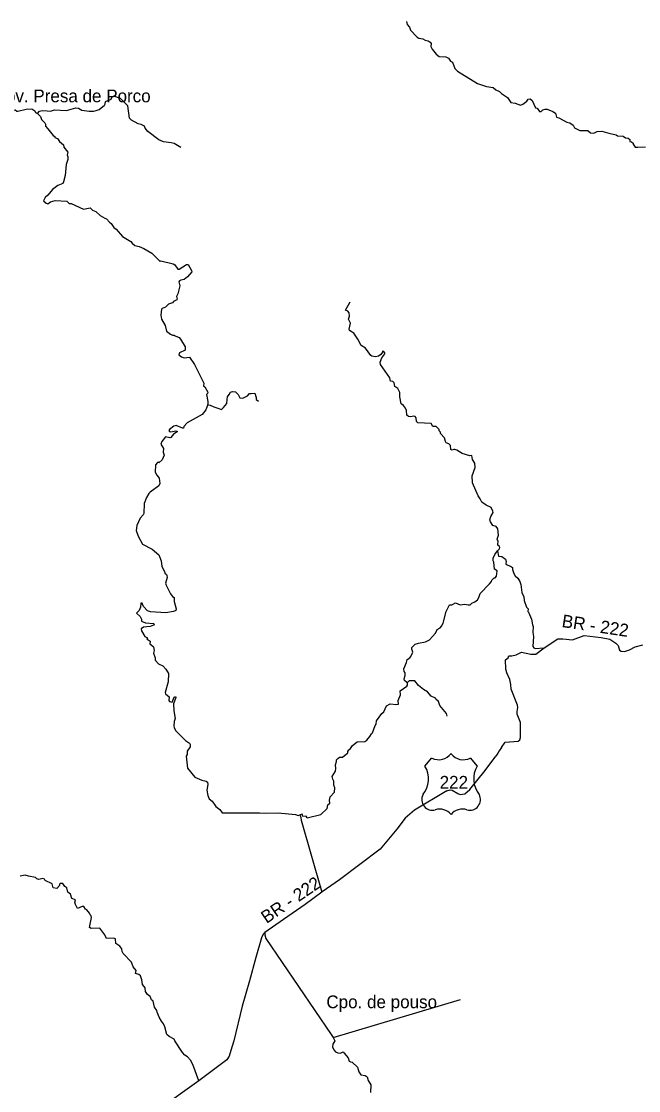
# Model space of a CAD drawing. Extents: x 332 to 501, y 9447 to 9559.
# Drawn here: x 359.78 to 378.21, y 9525.86 to 9557.78 of the extents above; entities that cross this region are included whole.
import ezdxf

# ---------------------------------------------------------------- set-up
doc = ezdxf.new("R2010")
doc.units = 0
for name, color, linetype in [('Level 1', 7, 'Continuous'), ('Level 12', 7, 'Continuous'), ('Level 13', 7, 'Continuous'), ('Level 19', 7, 'Continuous'), ('Level 2', 7, 'Continuous'), ('Level 31', 7, 'Continuous'), ('Level 5', 7, 'Continuous'), ('Level 6', 7, 'Continuous')]:
    doc.layers.add(name, color=color, linetype=linetype)

msp = doc.modelspace()

# ---------------------------------------------------------------- linework, layer by layer
at = {"layer": 'Level 1'}
msp.add_lwpolyline([(369.0885, 9527.4387), (372.8897, 9528.58)], dxfattribs=at)
at = {"layer": 'Level 12'}
for p, q in [((372.6121, 9535.9185), (372.6161, 9535.9145)), ((372.6121, 9535.9185), (372.6161, 9535.9145)), ((371.8321, 9535.5445), (372.0411, 9535.7875)), ((371.8321, 9535.5445), (372.0411, 9535.7875)), ((373.1841, 9535.7875), (373.3931, 9535.5465)), ((373.1841, 9535.7875), (373.3931, 9535.5465))]:
    msp.add_line(p, q, dxfattribs=at)
for centre, radius, start, end in [((372.2495, 9536.1884), 0.4521, 242.52866, 323.41613), ((372.2495, 9536.1884), 0.4521, 242.52866, 323.41613), ((372.9754, 9536.1884), 0.4521, 217.23652, 297.49118), ((372.9754, 9536.1884), 0.4521, 217.23652, 297.49118), ((371.2005, 9535.1628), 0.7384, 320.67545, 31.14191), ((371.2005, 9535.1628), 0.7384, 320.67545, 31.14191), ((374.0245, 9535.1628), 0.7384, 148.68697, 219.32478), ((374.0245, 9535.1628), 0.7384, 148.68697, 219.32478), ((372.0517, 9534.5464), 0.3163, 151.50036, 286.50661), ((372.0517, 9534.5464), 0.3163, 151.50036, 286.50661), ((373.1732, 9534.5464), 0.3163, 253.49418, 28.49966), ((373.1732, 9534.5464), 0.3163, 253.49418, 28.49966), ((372.2725, 9533.8299), 0.4335, 38.34717, 107.68664), ((372.2725, 9533.8299), 0.4335, 38.34717, 107.68664), ((372.9524, 9533.8299), 0.4335, 72.31282, 141.65284), ((372.9524, 9533.8299), 0.4335, 72.31282, 141.65284)]:
    msp.add_arc(centre, radius, start, end, dxfattribs=at)
at = {"layer": 'Level 2'}
for points in [[(375.39, 9539.0796), (375.7987, 9539.3431), (375.95, 9539.3431), (376.2403, 9539.3129), (376.5828, 9539.4448), (377.091, 9539.3843), (377.3572, 9539.3359), (377.5327, 9539.2148), (377.5992, 9539.1482), (377.6416, 9539.009), (377.696, 9538.9727), (377.7868, 9538.9666), (377.938, 9539.0211), (378.1074, 9539.1058), (378.3373, 9539.1664)], [(374.2337, 9538.7219), (374.3165, 9538.7741), (374.3407, 9538.8346), (374.4314, 9538.8346), (374.5585, 9538.8649), (374.7158, 9538.9436), (374.9941, 9538.8831), (375.1393, 9538.8891), (375.39, 9539.0796)], [(374.2322, 9536.2626), (374.6163, 9536.2883), (374.6663, 9536.3262), (374.6874, 9536.3973), (374.686, 9536.8457), (374.5861, 9537.0939), (374.5816, 9537.1712), (374.6043, 9537.2998), (374.5937, 9537.3604), (374.4061, 9537.8408), (374.4001, 9537.983), (374.3714, 9538.1314), (374.2761, 9538.3284), (374.2443, 9538.4404), (374.2337, 9538.7219)], [(374.1199, 9536.0998), (374.2322, 9536.2626)], [(374.0053, 9535.9285), (373.9444, 9535.8414)], [(374.0441, 9536.0045), (374.0053, 9535.9285)], [(374.1199, 9536.0998), (374.0441, 9536.0045)], [(372.4859, 9534.804), (372.5811, 9534.836), (372.6401, 9534.8224), (372.8125, 9534.7241), (372.8851, 9534.7014), (373.0243, 9534.7165), (373.172, 9534.8448), (373.6284, 9535.4114), (373.9444, 9535.8414)], [(372.4859, 9534.804), (371.5201, 9534.2336), (371.2371, 9533.9875), (370.9969, 9533.6593), (370.4926, 9533.0669), (369.2759, 9532.1543), (368.7578, 9531.7888)], [(368.7527, 9531.785), (368.2572, 9531.4161), (367.6033, 9530.9641)], [(368.7578, 9531.7888), (368.7527, 9531.785)], [(367.6033, 9530.9641), (367.0502, 9530.5818)], [(367.0502, 9530.5818), (367.0001, 9530.5261), (366.9531, 9530.4173)], [(366.9531, 9530.4173), (366.7858, 9529.8262)], [(366.7858, 9529.8262), (366.5886, 9529.129)], [(366.5886, 9529.129), (366.3772, 9528.3818), (366.1272, 9527.3404)], [(366.1272, 9527.3404), (366.0355, 9527.0502)], [(366.0355, 9527.0502), (365.9822, 9526.8823)], [(365.9822, 9526.8823), (365.9168, 9526.7768), (365.0749, 9526.1487)], [(365.0749, 9526.1487), (363.8547, 9525.2686)]]:
    msp.add_lwpolyline(points, dxfattribs=at)
at = {"layer": 'Level 5'}
for points in [[(371.2784, 9557.7817), (371.301, 9557.6897), (371.3715, 9557.6127), (371.4027, 9557.5192), (371.5979, 9557.3058), (371.6472, 9557.2779), (371.7636, 9557.2648), (371.8358, 9557.2238), (371.9261, 9557.2008), (371.9835, 9557.1615), (372.0179, 9557.1221), (372.0081, 9557.0351), (372.0425, 9556.9515), (372.1639, 9556.8055), (372.2558, 9556.7284), (372.4592, 9556.7218), (372.5396, 9556.6808), (372.5971, 9556.5889), (372.6594, 9556.5676), (372.7267, 9556.374), (372.807, 9556.2936), (373.3976, 9555.9295), (373.6667, 9555.8327), (373.8719, 9555.8098), (373.9474, 9555.7343), (374.0589, 9555.6901), (374.1229, 9555.6277), (374.2968, 9555.5063), (374.3936, 9555.3603), (374.5249, 9555.3357), (374.6857, 9555.2815), (374.7595, 9555.311), (374.8793, 9555.4029), (374.9186, 9555.4587), (374.976, 9555.4685), (375.0368, 9555.4193), (375.1368, 9555.1995), (375.1877, 9555.1946), (375.2533, 9555.0912), (375.3042, 9555.0912), (375.355, 9555.1388), (375.4207, 9555.1585), (375.4863, 9555.1585), (375.6535, 9555.093), (375.7274, 9555.0389), (375.7651, 9554.9175), (375.8258, 9554.9027), (376.067, 9554.7731), (376.154, 9554.7567), (376.259, 9554.6813), (376.3016, 9554.6009), (376.4624, 9554.5254), (376.6954, 9554.5238), (376.779, 9554.4565), (376.8775, 9554.4467), (376.971, 9554.4959), (377.1137, 9554.5074), (377.3189, 9554.4417), (377.5453, 9554.3924), (377.5814, 9554.3678), (377.7537, 9554.3514), (377.8226, 9554.3071), (377.903, 9554.2907), (377.9473, 9554.2546), (377.9506, 9554.1923), (377.9965, 9554.1825), (378.0506, 9554.1464)], [(358.2122, 9556.4015), (358.2422, 9556.2956), (358.3848, 9556.148), (358.8126, 9555.9561), (358.847, 9555.902), (358.8568, 9555.8085), (358.9208, 9555.715), (359.0716, 9555.6432), (359.1011, 9555.6039), (359.1208, 9555.4612), (359.1405, 9555.4169), (359.3175, 9555.2053), (359.3372, 9555.161), (359.3913, 9555.1315), (359.4503, 9555.1266), (359.5929, 9555.1413), (359.6421, 9555.102), (359.6765, 9555.102), (359.9174, 9555.161), (360.0945, 9555.166), (360.1781, 9555.1069), (360.2027, 9555.0577), (360.2568, 9555.0331)], [(363.0676, 9554.8353), (363.0087, 9554.896), (362.955, 9555.2641), (362.7359, 9555.4751), (362.5376, 9555.5495), (362.4756, 9555.5164), (362.4508, 9555.4503), (362.2855, 9555.3758), (362.2648, 9555.2807)], [(360.2568, 9555.0331), (360.3158, 9555.0971), (360.3994, 9555.1167), (360.5512, 9555.1088)], [(360.5512, 9555.1088), (360.6511, 9555.1014), (360.7696, 9555.1384), (361.1286, 9555.1199), (361.4025, 9555.1976), (361.4802, 9555.1865), (361.5801, 9555.1347), (361.8022, 9555.1014), (361.9354, 9555.1014), (362.0168, 9555.1162), (362.0983, 9555.1532), (362.2648, 9555.2807)], [(360.2568, 9555.0331), (360.3453, 9554.9461), (360.3797, 9554.8476), (360.483, 9554.7492), (360.5026, 9554.7099), (360.5026, 9554.6557), (360.5666, 9554.5721), (360.7239, 9554.3753), (360.7731, 9554.3458), (360.7731, 9554.3113), (360.8567, 9554.2867), (360.9206, 9554.1932), (361.0337, 9554.0948), (361.0435, 9554.0308), (361.1654, 9553.8803), (361.1507, 9553.7967), (361.1704, 9553.7327), (361.1704, 9553.654), (361.1212, 9553.5113), (361.0868, 9553.1816), (361.0376, 9552.9897), (361.013, 9552.9455), (360.8655, 9552.8766), (360.713, 9552.7585), (360.5704, 9552.5888), (360.4917, 9552.5199), (360.4376, 9552.4215), (360.5163, 9552.3526), (360.5655, 9552.3329), (360.6442, 9552.392), (360.7868, 9552.4313), (361.1359, 9552.4166), (361.2048, 9552.3477), (361.2638, 9552.3428), (361.6375, 9552.1706), (361.8293, 9552.2099), (361.9059, 9552.1426), (361.9993, 9552.1032), (362.1272, 9551.9851), (362.2698, 9551.9015), (362.3239, 9551.8867), (362.4124, 9551.7834)], [(364.5411, 9554.0155), (364.3386, 9554.1353), (364.2518, 9554.1601), (364.0204, 9554.1849), (363.8881, 9554.2469), (363.5542, 9554.4948), (363.4757, 9554.59), (363.4592, 9554.652), (363.3517, 9554.7016), (363.2649, 9554.7223), (363.0676, 9554.8353)], [(378.0506, 9554.1464), (378.0506, 9554.1136), (378.108, 9554.0298), (378.1868, 9554.0298)], [(378.1868, 9554.0298), (378.4165, 9554.038)], [(362.4124, 9551.7834), (362.4566, 9551.7489), (362.5353, 9551.6259), (362.6091, 9551.5767), (362.8009, 9551.3602), (363.0516, 9551.2077), (363.0861, 9551.1585), (363.1647, 9551.0945), (363.2975, 9551.0601), (363.4401, 9551.001), (363.6712, 9550.8632), (363.927, 9550.6123), (363.945, 9550.633), (364.3139, 9550.5444), (364.3581, 9550.51), (364.4515, 9550.382), (364.4958, 9550.382), (364.7122, 9550.5247), (364.7564, 9550.5198), (364.8644, 9550.3389)], [(364.8644, 9550.3389), (364.8646, 9550.3033), (364.7368, 9550.1557), (364.6433, 9550.077), (364.545, 9550.0573), (364.5007, 9550.0376), (364.4811, 9550.0081), (364.5106, 9549.8827), (364.4515, 9549.6465), (364.4122, 9549.5629), (364.4319, 9549.4891), (364.4171, 9549.4645), (364.3237, 9549.4153), (364.2893, 9549.3808), (364.1762, 9549.3365), (364.0877, 9549.248), (363.9795, 9549.2086), (363.9647, 9549.1889), (363.945, 9549.0118), (363.9647, 9548.8937), (364.0778, 9548.6969), (364.1122, 9548.5296), (364.2303, 9548.441), (364.2893, 9548.4164), (364.3434, 9548.4164), (364.3729, 9548.3899), (364.4958, 9548.3407), (364.5351, 9548.2964), (364.6674, 9548.0602)], [(370.2146, 9547.8094), (370.0528, 9548.0195), (369.9222, 9548.1019), (369.8285, 9548.2972), (369.7035, 9548.4762), (369.5786, 9548.5473), (369.5701, 9548.5899), (369.607, 9548.7689), (369.5502, 9548.8911), (369.5758, 9548.9849), (369.571, 9549.0747), (369.5255, 9549.1258), (369.4602, 9549.1599), (369.5965, 9549.4128)], [(364.6674, 9548.0602), (364.6696, 9547.965), (364.5042, 9547.8822), (364.4858, 9547.8271), (364.5593, 9547.7628), (364.642, 9547.7352), (364.7983, 9547.7536), (364.945, 9547.5372), (365.2263, 9546.978), (365.2228, 9546.8972), (365.2619, 9546.8687), (365.3474, 9546.7084), (365.3367, 9546.6692), (365.3047, 9546.6442), (365.3474, 9546.434), (365.3474, 9546.3378), (365.2869, 9546.1881), (365.18, 9546.0398), (364.7278, 9545.7904), (364.6352, 9545.6835), (364.6174, 9545.6407), (364.5924, 9545.631), (364.4001, 9545.7166), (364.336, 9545.6952), (364.2043, 9545.599), (364.1865, 9545.5705), (364.2007, 9545.5384), (364.247, 9545.5277), (364.3895, 9545.5527), (364.4286, 9545.5491), (364.4322, 9545.5277), (364.3182, 9545.4564), (364.2434, 9545.3602), (364.2114, 9545.3495), (364.0867, 9545.378), (363.9692, 9545.2426), (363.9407, 9545.1536), (364.0262, 9545.0324), (364.0084, 9544.9184), (364.044, 9544.8257), (363.9835, 9544.6903), (363.8838, 9544.6048), (363.8802, 9544.6204), (363.841, 9544.6062), (363.784, 9544.5384)], [(370.5065, 9547.5378), (370.4966, 9547.61), (370.5417, 9547.7333), (370.6342, 9547.8567), (370.6365, 9547.8827), (370.6081, 9547.9254), (370.5607, 9547.9397), (370.5607, 9547.9065), (370.5132, 9547.8377), (370.4397, 9547.7831), (370.3567, 9547.7689), (370.2429, 9547.7903), (370.2146, 9547.8094)], [(371.2516, 9546.2322), (371.1955, 9546.3088), (371.1189, 9546.3649), (371.086, 9546.5684), (371.0821, 9546.7008), (371.0219, 9546.8243), (370.9352, 9546.8804), (370.9097, 9546.9927), (370.8688, 9547.0284), (370.8025, 9547.0386), (370.7821, 9547.1356), (370.5065, 9547.5378)], [(373.3261, 9544.5903), (373.2515, 9544.6981), (373.2349, 9544.8184), (373.1769, 9544.8101), (372.9407, 9544.8805), (372.7791, 9544.9801), (372.7252, 9544.9967), (372.6921, 9545.0008), (372.6465, 9544.9801), (372.6092, 9545.0008), (372.5942, 9545.1199), (372.5445, 9545.1655), (372.4692, 9545.2), (372.4446, 9545.234), (372.4201, 9545.3438), (372.3, 9545.4765), (372.2917, 9545.5179), (372.2585, 9545.5553), (372.2585, 9545.6009), (372.1674, 9545.6838), (372.072, 9545.6838), (372.0182, 9545.7792), (371.6204, 9545.7999), (371.5748, 9545.8331), (371.5665, 9545.9409), (371.5416, 9545.9823), (371.5043, 9545.9906), (371.3966, 9545.9699), (371.3386, 9545.9823), (371.2888, 9546.028), (371.2764, 9546.1606), (371.2516, 9546.2322)], [(363.784, 9544.5384), (363.7734, 9544.3247), (363.8197, 9544.2356), (363.8944, 9544.1465), (363.9158, 9543.979), (363.8838, 9543.9184), (363.6274, 9543.7296), (363.5811, 9543.681), (363.5134, 9543.5634), (363.4422, 9543.3853), (363.4315, 9543.0905), (363.4137, 9543.0478), (363.3282, 9542.948), (363.2249, 9542.7271), (363.2107, 9542.581), (363.2677, 9542.4135), (363.3994, 9542.169), (363.6879, 9542.0193), (363.8873, 9541.8554), (363.9514, 9541.6747), (363.9764, 9541.5036), (364.0618, 9541.3397), (364.0654, 9541.3041), (364.1081, 9541.2685), (364.1224, 9541.2335), (364.133, 9541.18), (364.0832, 9541.0054), (364.101, 9540.9449), (364.2328, 9540.6883), (364.2933, 9540.6135), (364.3432, 9540.5814), (364.3396, 9540.4648), (364.4037, 9540.2368), (364.3895, 9540.1905), (364.3182, 9540.1584), (364.0974, 9540.1228), (363.638, 9540.1477)], [(373.9986, 9541.9764), (374.0555, 9542.0354), (374.0679, 9542.0727), (374.0472, 9542.1142), (374.0099, 9542.1432), (374.0057, 9542.1723), (374.014, 9542.2552), (373.9933, 9542.3174), (374.0264, 9542.4418), (374.0057, 9542.6325), (373.956, 9542.6989), (373.8565, 9542.732), (373.7902, 9542.8398), (373.7737, 9542.8979), (373.8027, 9542.9974), (373.869, 9543.1135), (373.8607, 9543.1576), (373.811, 9543.2654), (373.6618, 9543.34), (373.5333, 9543.4271), (373.4836, 9543.5307), (373.4214, 9543.6137), (373.2557, 9544.0076), (373.2391, 9544.2108), (373.3344, 9544.4659), (373.3261, 9544.5903)], [(373.186, 9540.3645), (373.2294, 9540.4131), (373.322, 9540.4455), (373.3966, 9540.5118), (373.4421, 9540.5823), (373.4794, 9540.6984), (373.7612, 9540.9845), (373.8192, 9541.055), (373.8317, 9541.0965), (373.9021, 9541.1628), (373.9311, 9541.167), (373.9684, 9541.2209), (373.985, 9541.3743), (373.9063, 9541.4282), (373.8938, 9541.6355), (373.8731, 9541.677), (373.8648, 9541.7516), (373.9146, 9541.8594), (373.9986, 9541.9764)], [(373.9986, 9541.9764), (374.0302, 9541.8188), (374.1244, 9541.8079), (374.2368, 9541.7209), (374.2585, 9541.6593), (374.2476, 9541.5905), (374.2621, 9541.5651), (374.3883, 9541.5144), (374.4419, 9541.4761), (374.4445, 9541.4173), (374.4854, 9541.2997), (374.5263, 9541.2307), (374.6081, 9541.154), (374.6643, 9541.062), (374.695, 9540.9649), (374.7231, 9540.7246), (374.7844, 9540.6029), (374.7947, 9540.493), (374.8688, 9540.296), (374.9122, 9540.2398), (374.9046, 9540.1617), (374.9276, 9540.1438), (375.017, 9539.9315), (375.04, 9539.7678), (375.063, 9539.709), (375.0554, 9539.5325), (375.0733, 9539.4148), (375.0503, 9539.1165), (375.0861, 9539.073), (375.1244, 9539.0577), (375.39, 9539.0796)], [(363.3985, 9540.379), (363.3816, 9540.4114), (363.346, 9540.4114), (363.3389, 9540.2867), (363.2962, 9540.1869), (363.2214, 9540.1121), (363.3282, 9540.0087), (363.3674, 9539.9339), (363.3638, 9539.8698), (363.4885, 9539.8234), (363.7306, 9539.8056), (363.7484, 9539.7842), (363.7271, 9539.7557), (363.6238, 9539.713), (363.4264, 9539.6982), (363.3603, 9539.6417), (363.3674, 9539.5802), (363.4635, 9539.4128), (363.549, 9539.3771), (363.5276, 9539.3486), (363.5383, 9539.3308), (363.6202, 9539.2774), (363.6131, 9539.1883), (363.6487, 9539.174), (363.7199, 9539.1028), (363.7449, 9538.9923), (363.7235, 9538.9139), (363.7769, 9538.7821), (363.7769, 9538.7037), (363.8731, 9538.6003), (364.0048, 9538.5433), (364.0974, 9538.4436), (364.1687, 9538.3153), (364.1651, 9538.0658), (364.0725, 9537.74), (364.0832, 9537.7008), (364.1971, 9537.6117), (364.1829, 9537.5084), (364.2007, 9537.4763), (364.2826, 9537.455), (364.3467, 9537.6046), (364.3823, 9537.626), (364.3966, 9537.5975)], [(363.638, 9540.1477), (363.5419, 9540.1798), (363.4244, 9540.3116), (363.3985, 9540.379)], [(371.2978, 9538.7294), (371.3774, 9538.7815), (371.4106, 9538.8229), (371.4686, 9538.9472), (371.4354, 9539.0343), (371.4396, 9539.0881), (371.4686, 9539.1213), (371.539, 9539.1876), (371.6385, 9539.2207), (371.8457, 9539.258), (371.9688, 9539.3196), (372.1512, 9539.5145), (372.1926, 9539.6223), (372.2838, 9539.6762), (372.3252, 9539.7218), (372.3791, 9539.8089), (372.4661, 9540.1655), (372.5697, 9540.3562), (372.6319, 9540.3562), (372.7479, 9540.4226), (372.8793, 9540.3604), (373.0202, 9540.3811), (373.1238, 9540.3604), (373.186, 9540.3645)], [(371.2145, 9538.367), (371.2, 9538.4539), (371.2761, 9538.6351), (371.2978, 9538.7294)], [(371.3123, 9538.0372), (371.2906, 9538.0372), (371.2254, 9538.0988), (371.2145, 9538.1495), (371.2399, 9538.251), (371.2399, 9538.3343), (371.2145, 9538.367)], [(369.1887, 9535.6965), (369.1951, 9535.7314), (369.2281, 9535.7699), (369.2832, 9535.8085), (369.3713, 9535.814), (369.531, 9535.9463), (369.531, 9535.9849), (369.5586, 9536.0289), (369.5916, 9536.04), (369.6687, 9536.1612), (369.8064, 9536.2659), (370.0377, 9536.2824), (370.0983, 9536.321), (370.1864, 9536.4312), (370.2305, 9536.5139), (370.269, 9536.5414), (370.3406, 9536.7563), (370.3792, 9536.8004), (370.3847, 9536.8941), (370.5444, 9537.1179), (370.5995, 9537.1675), (370.6876, 9537.3438), (370.7905, 9537.4066), (370.985, 9537.3824), (371.0401, 9537.3934), (371.0346, 9537.5091), (371.1062, 9537.6745), (371.0951, 9537.7957), (371.2879, 9537.928), (371.3154, 9537.961), (371.3123, 9538.0372)], [(372.4941, 9537.0369), (372.4779, 9537.1144), (372.2787, 9537.3572), (372.2316, 9537.4732), (372.1555, 9537.542), (372.1447, 9537.5783), (372.0143, 9537.6326), (371.9129, 9537.7595), (371.7904, 9537.8306), (371.6419, 9537.9538), (371.5332, 9538.0879), (371.363, 9538.0915), (371.3123, 9538.0372)], [(364.3966, 9537.5975), (364.3254, 9537.4051), (364.3325, 9537.1948), (364.3752, 9536.9704), (364.3396, 9536.8777), (364.3289, 9536.7494), (364.3396, 9536.6853), (364.3895, 9536.6014), (364.685, 9536.3128), (364.8026, 9536.2273), (364.8239, 9536.1917), (364.8204, 9536.124), (364.7349, 9535.9886), (364.7278, 9535.8888), (364.7028, 9535.8425), (364.742, 9535.4846), (364.9592, 9535.2102), (365.1694, 9535.1247), (365.2976, 9535.0926), (365.3367, 9535.0641), (365.3439, 9534.9928), (365.3162, 9534.8273)], [(368.7193, 9534.0962), (368.9117, 9534.2831), (368.9337, 9534.3932), (368.9888, 9534.4428), (368.9832, 9534.5309), (368.9998, 9534.6245), (369.1319, 9534.7677), (369.1375, 9534.8999), (369.1154, 9534.9715), (369.1154, 9535.0982), (369.0824, 9535.1533), (369.0604, 9535.2359), (369.1595, 9535.3901), (369.1705, 9535.4727), (369.1595, 9535.5828), (369.187, 9535.6875)], [(369.187, 9535.6875), (369.1887, 9535.6965)], [(365.3162, 9534.8273), (365.3425, 9534.6631), (365.386, 9534.5728), (365.473, 9534.4992), (365.5901, 9534.3386), (365.7105, 9534.2516), (365.7774, 9534.1513), (366.8935, 9534.155), (367.0708, 9534.1383), (367.4454, 9534.155), (367.97, 9534.1048), (368.0436, 9534.0747), (368.0968, 9534.0928)], [(368.3092, 9534.003), (368.2825, 9534.0502), (368.184, 9534.0387), (368.161, 9534.106), (368.0968, 9534.0928)], [(368.0968, 9534.0928), (368.1225, 9534.0137)], [(368.1225, 9534.0137), (368.1358, 9533.9355)], [(368.3092, 9534.003), (368.7193, 9534.0962)], [(368.1358, 9533.9355), (368.7527, 9531.785)], [(367.0502, 9530.5818), (367.046, 9530.5032), (367.0794, 9530.4028), (369.0272, 9527.5296)], [(369.0272, 9527.5296), (369.0885, 9527.4387)], [(369.098, 9527.4245), (369.1446, 9527.3387), (369.0758, 9527.2388), (369.0736, 9527.1588), (369.1113, 9527.0722), (369.1624, 9527.0167), (369.2289, 9526.9834), (369.3066, 9526.9746), (369.3843, 9527.0123), (369.422, 9526.979), (369.5374, 9526.8373), (369.5706, 9526.7352), (369.6039, 9526.7107), (369.6572, 9526.7071), (369.8192, 9526.5517), (369.8591, 9526.4184), (369.921, 9526.3282)], [(369.0885, 9527.4387), (369.098, 9527.4245)], [(369.921, 9526.3282), (370.0497, 9526.3122), (370.1052, 9526.27), (370.1407, 9526.1546), (370.2183, 9526.0324), (370.2094, 9525.8015)]]:
    msp.add_lwpolyline(points, dxfattribs=at)
at = {"layer": 'Level 6'}
msp.add_lwpolyline([(369.9259, 9548.1215), (369.9259, 9548.1215), (369.9259, 9548.1215)], close=True, dxfattribs=at)
for points in [[(365.3474, 9546.3378), (365.3369, 9546.3307), (365.4195, 9546.3252), (365.5297, 9546.2701), (365.651, 9546.2315), (365.7557, 9546.1929), (365.8108, 9546.2535), (365.91, 9546.3693), (365.921, 9546.4905), (365.9375, 9546.5676), (365.9816, 9546.6393), (366.0257, 9546.7109), (366.0808, 9546.7329), (366.169, 9546.7219), (366.2516, 9546.6448), (366.3012, 9546.5456), (366.3949, 9546.5291), (366.3949, 9546.5291), (366.5327, 9546.6007), (366.5878, 9546.6668), (366.5878, 9546.6668), (366.6429, 9546.6668), (366.7531, 9546.6778), (366.7861, 9546.5511), (366.7861, 9546.5511), (366.7917, 9546.496), (366.8578, 9546.4409), (366.8578, 9546.4409)], [(361.6415, 9531.353), (361.5935, 9531.353), (361.4547, 9531.2889), (361.3907, 9531.4117), (361.3747, 9531.4811), (361.3907, 9531.5506), (361.2893, 9531.5933), (361.2412, 9531.7214), (361.1612, 9531.7855), (361.1345, 9531.9137), (361.0811, 9531.9511), (361.0171, 9532.0365), (360.9477, 9532.0418), (360.921, 9532.0205), (360.9157, 9531.9778), (360.8357, 9531.887), (360.7289, 9531.9137), (360.6969, 9532.0312), (360.4941, 9532.1326), (360.4728, 9532.17), (360.4194, 9532.186), (360.2966, 9532.1593), (360.2433, 9532.1753), (360.2006, 9532.218), (359.9871, 9532.2554), (359.8964, 9532.2928), (359.7417, 9532.263)], [(365.0749, 9526.1487), (364.8996, 9526.6388), (364.8249, 9526.7669), (364.7395, 9526.8683), (364.6648, 9526.9163), (364.5954, 9526.991), (364.3606, 9527.3379), (364.3393, 9527.3966), (364.1899, 9527.4713), (364.1258, 9527.53), (364.0618, 9527.7648), (364.0244, 9527.8502), (363.9604, 9527.9249), (363.891, 9528.0476), (363.8323, 9528.1971), (363.827, 9528.2504), (363.7576, 9528.3516), (363.7149, 9528.5224), (363.6615, 9528.5705), (363.6295, 9528.6666), (363.5495, 9528.7254), (363.4854, 9528.8108), (363.4748, 9528.9283), (363.4, 9529.0244), (363.3787, 9529.1632), (363.336, 9529.2807), (363.288, 9529.3234), (363.1919, 9529.3555), (363.2026, 9529.4389), (363.1172, 9529.5511), (363.0692, 9529.6899), (362.8183, 9529.9516), (362.7863, 9530.0103), (362.781, 9530.0851), (362.7223, 9530.1705), (362.5995, 9530.2506), (362.5889, 9530.3841), (362.5302, 9530.4054), (362.3167, 9530.4001), (362.274, 9530.5122), (362.1192, 9530.7098), (361.8656, 9530.6962), (361.8176, 9530.7282), (361.871, 9531.0272), (361.8603, 9531.0753), (361.8283, 9531.102), (361.8176, 9531.1554), (361.7322, 9531.2569), (361.6949, 9531.2729), (361.6415, 9531.353)]]:
    msp.add_lwpolyline(points, dxfattribs=at)

# ---------------------------------------------------------------- texts
at = {"layer": 'Level 13'}
msp.add_text('Cpo. de pouso', height=0.38, dxfattribs=at).set_placement((368.8875, 9528.3168))
at = {"layer": 'Level 19'}
msp.add_text('Est. Ferrov. Presa de Porco', height=0.38, dxfattribs=at).set_placement((357.3703, 9555.3665))
at = {"layer": 'Level 31'}
for s, rotation, p in [('BR - 222', 351.37623, (375.9012, 9539.701)), ('222', 0.00001, (372.2708, 9534.8728)), ('BR - 222', 34.21656, (367.1012, 9530.8307))]:
    msp.add_text(s, height=0.38, rotation=rotation, dxfattribs=at).set_placement(p)

doc.saveas('drawing.dxf')
